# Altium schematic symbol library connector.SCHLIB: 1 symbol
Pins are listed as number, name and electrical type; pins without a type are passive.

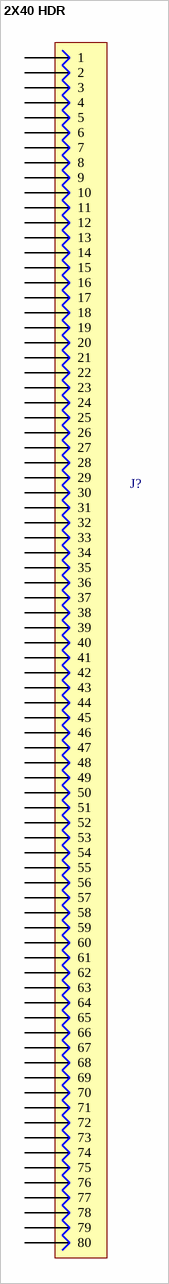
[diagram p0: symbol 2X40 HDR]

## 2X40 HDR
designator J?
HEADER, 80 PIN; NAME: 80 PIN HEADER
footprint H2X40 (Footprint not found)
pins: 1, 2, 3, 4, 5, 6, 7, 8, 9, 10, 11, 12, 13, 14, 15, 16, 17, 18, 19, 20, 21, 22, 23, 24, 25, 26, 27, 28, 29, 30, 31, 32, 33, 34, 35, 36, 37, 38, 39, 40, 41, 42, 43, 44, 45, 46, 47, 48, 49, 50, 51, 52, 53, 54, 55, 56, 57, 58, 59, 60, 61, 62, 63, 64, 65, 66, 67, 68, 69, 70, 71, 72, 73, 74, 75, 76, 77, 78, 79, 80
